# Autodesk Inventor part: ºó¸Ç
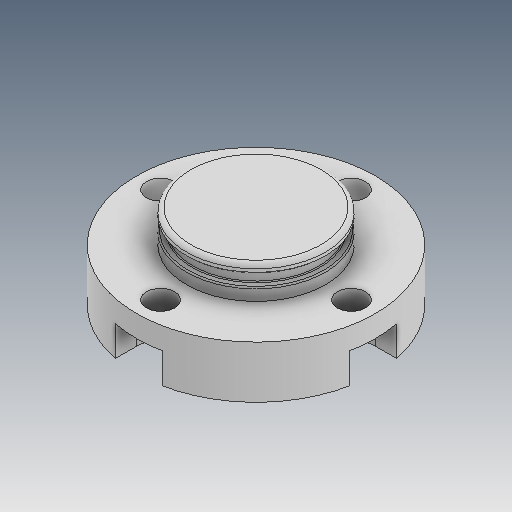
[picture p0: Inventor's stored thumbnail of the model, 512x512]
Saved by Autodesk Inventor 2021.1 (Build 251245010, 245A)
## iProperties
Created: 2013-04
Part Number: ºó¸Ç
Material: Ogólny
Document SubType Name: Modeling
Designer: user
Density: 1 g/cm^3
Appearance: Domyślna
Author: user
Revision Number: ÈÎºÎ
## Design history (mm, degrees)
feature "À­Éì2"
node "Bryła1"
